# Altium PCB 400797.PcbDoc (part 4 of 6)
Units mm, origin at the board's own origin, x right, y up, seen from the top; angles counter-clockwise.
Board outline 155 x 63.5 mm, 4 copper layers (Top Layer, Mid-Layer 1, Mid-Layer 2, Bottom Layer), stack 1.514 mm thick; 317 components, 286 nets, 1519 pads, 2174 vias.
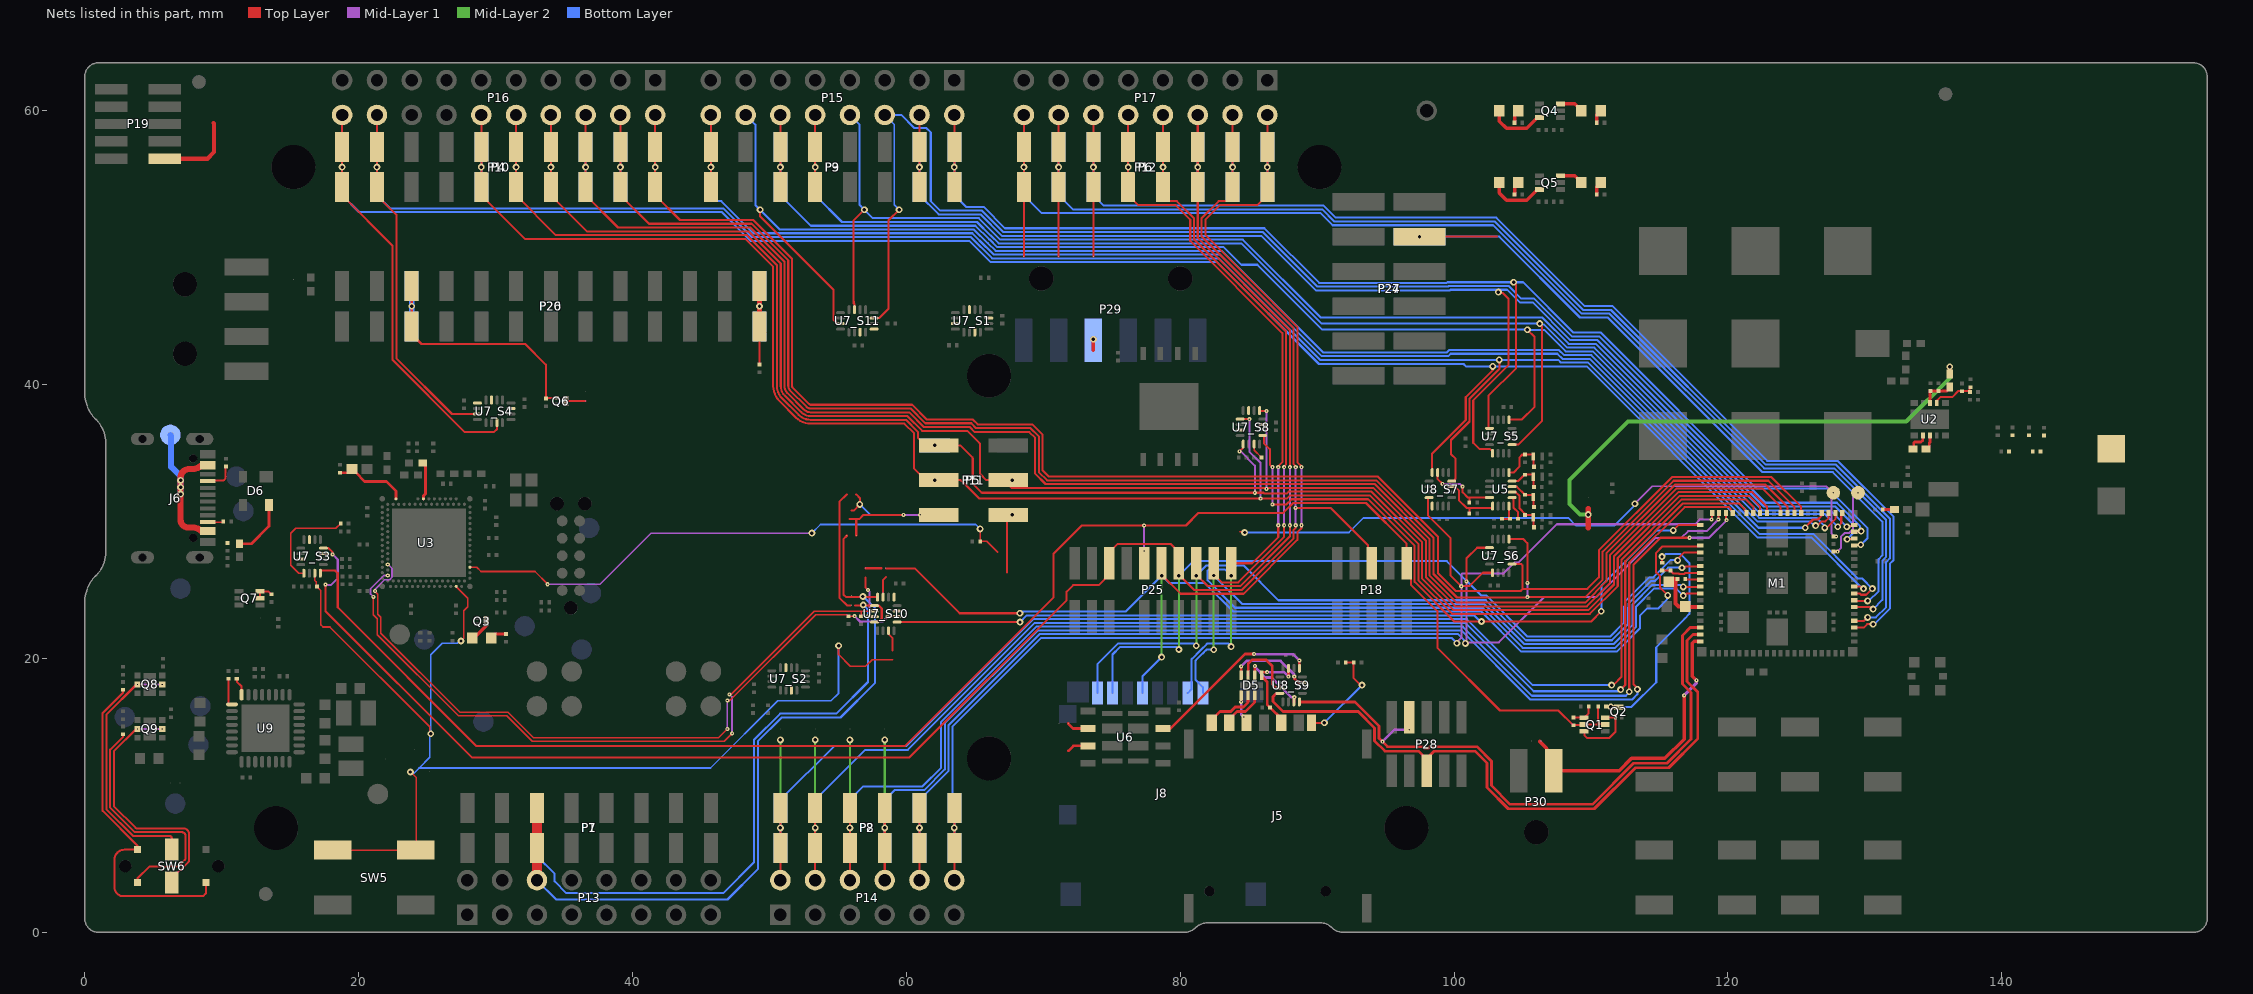
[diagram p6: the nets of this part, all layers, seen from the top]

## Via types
v1: diameter 0.5, hole 0.25, Top Layer to Bottom Layer, tented both sides, 1623 vias
v2: diameter 0.3, hole 0.1, Top Layer to Mid-Layer 1, tented top, 445 vias
v3: diameter 0.3, hole 0.1, Top Layer to Mid-Layer 1, tented both sides, 97 vias
v4: diameter 0.61, hole 0.305, Top Layer to Bottom Layer, tented both sides, 9 vias

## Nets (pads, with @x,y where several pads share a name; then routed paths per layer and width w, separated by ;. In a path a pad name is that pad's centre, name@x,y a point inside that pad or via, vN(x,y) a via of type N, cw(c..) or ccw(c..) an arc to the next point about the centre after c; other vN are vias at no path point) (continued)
NC.CH4_S3: R19.2 U7_S3.13 | length 7.5
  Top Layer w0.125: U7_S3.13@16,26.225 15.625,26.225 15.05,26.8 15.05,29.147 15.412,29.509 18.34,29.509 R19.2@18.69,29.859
NC.CH4_S4: U7_S4.13
NC.CH4_S7: U8_S7.13
NC.CH4_S9: U6.7 U8_S9.13 | length 13
  Top Layer w0.2: U6.7@78.75,14.885 79.285,14.885 84.725,20.325 v2(85.4,20.325) ; U8_S9.13@88.7,19.275 v2(88.7,19.85)
  Mid-Layer 1 w0.2: v2(85.4,20.325) 85.415,20.31 88.24,20.31 v2(88.7,19.85)
NC.CH4_S10: U7_S10.13
NC.CH4_S11: U7_S11.13
NetA1_1: A1.1 C20.2 L2.2
NetC7_1: C7.1 FB1.2 M1.14 R1.1 | length 4.5
  Top Layer w0.3: C7.1@115.675,25.6 115.875,25.8 R1.1@116.315,25.8 116.175,25.66 116.175,24.025 116.4,23.8 FB1.2@116.875,23.8 116.925,23.75 M1.14@117.975,23.75
NetC10_1: C10.1 M1.9 R2.2 | length 2.9
  Top Layer w0.15: R2.2@115.125,26.475 115.14,26.475 R2.2@115.2,26.415 C10.1@115.8,26.415 ; C10.1@115.875,26.34 116.015,26.2 116.411,26.2 116.434,26.177 116.83,26.177 116.903,26.25 M1.9@117.975,26.25
NetC14_2: C14.2 C15.2 FB3.1 U2.3 | length 2.5
  Top Layer w0.2: U2.3@134.747,38.653 C14.2@134.747,39.534 ; C14.2@134.797,39.534 C14.2@134.8,39.537 C15.2@135.375,39.537 135.987,39.537 136.2,39.75 FB3.1@136.2,39.825 FB3.1@136.2,39.9
NetC16_2: C16.2 C17.2 R6.2 U2.2 | length 3.1
  Top Layer w0.15: U2.2@135.247,38.653 135.247,38.819 135.513,39.085 136.385,39.085 136.837,39.537 137.595,39.537 137.625,39.567 137.625,39.755 137.685,39.815 C16.2@137.7,39.815
NetC19_2: C19.2 L4.2 | length 0.8
  Top Layer w0.203: C19.2@131.315,30.88 L4.2@132.155,30.88
NetC20_1: C20.1 C22.2 C23.2 L1.2
NetC36_2: C36.2 U3.A15 | length 2.7
  Top Layer w0.225: C36.2@24.675,34.264 24.875,34.064 24.875,32.009 24.725,31.859 U3.A15@24.725,31.659
NetC37_1: C37.1 R21.2 U3.A5 | length 5.3
  Top Layer w0.15: U3.A5@22.725,31.659 U3.A5@22.75,31.684
  Top Layer w0.18: U3.A5@22.745,31.684 22.745,31.774
  Top Layer w0.2: R21.2@18.625,33.565 19.794,33.565 20.434,32.925 22.026,32.925 22.725,32.225 U3.A5@22.725,31.659
NetC44_1: C44.1 D1.3 R53.1 U5.2 | length 3.6
  Top Layer w0.15: U5.2@104.235,32.15 104.516,32.15 104.78,31.887 104.78,30.963 105.174,30.568 C44.1@105.174,30.476 D1.3@105.784,30.476 ; D1.3@105.789,30.318 105.789,29.621 R53.1@105.829,29.581
NetC45_2: C45.2 D2.3 R55.1 U5.3 | length 2.6
  Top Layer w0.15: U5.3@104.235,32.55 104.581,32.55 C45.2@105.182,31.949 ; C45.2@105.174,31.949 C45.2@105.182,31.949 ; D2.3@105.784,31.949 C45.2@105.182,31.949 ; D2.3@105.789,31.791 105.789,31.095 R55.1@105.829,31.055
NetC46_2: C46.2 D3.3 R57.1 U5.4 | length 2.5
  Top Layer w0.15: U5.4@104.235,32.95 104.67,32.95 105.142,33.422 C46.2@105.174,33.422 D3.3@105.784,33.422 ; D3.3@105.789,33.264 105.789,32.568 R57.1@105.829,32.528
NetC47_2: C47.2 D4.3 R61.1 U5.5 | length 3.5
  Top Layer w0.15: U5.5@104.01,33.575 104.34,33.575 104.771,34.006 104.771,34.669 104.997,34.896 C47.2@105.174,34.896 D4.3@105.784,34.896 ; D4.3@105.789,34.738 105.789,34.041 R61.1@105.829,34.001
NetC50_2: C50.2 D6.4 FB2.1 J6.A4 J6.A9 TP17.1 | length 16.9
  Top Layer w0.2: FB2.1@11.24,28.435 cw(c11.24,28.375) FB2.1@11.3,28.375 12.165,28.375 13.447,29.657 D6.4@13.447,31.209
  Top Layer w0.45: J6.A9@8.985,29.3 8.489,29.3 ccw(c7.915,28.81) 7.896,29.565 7.535,29.565 cw(c7.535,30.1) 7,30.1 v1(7,32) v1(7,32.5) v1(7,33) 7,33.2 cw(c7.635,33.2) 7.635,33.835 7.896,33.835 ccw(c7.915,34.59) 8.489,34.1 J6.A4@8.985,34.1
  Bottom Layer w0.45: TP17.1@6.248,36.324 6.3,36.272 6.3,34 7,33.3 v1(7,33) v1(7,32.5) v1(7,32)
NetD5_1: D5.1 J5.C2 | length 1.7
  Top Layer w0.2: v2(84.45,16.825) D5.1@84.45,17.325
  Mid-Layer 1 w0.2: v2(84.45,16.825) 84.45,15.925 v2(84.65,15.725)
NetD5_2: D5.2 J5.C3 | length 3.9
  Top Layer w0.2: J5.C3@82.3,15.3 82.3,15.525 82.9,16.125 83.69,16.125 84.015,16.45 84.619,16.45 84.95,16.781 D5.2@84.95,17.325
NetD5_3: D5.3 J5.C7 | length 3.2
  Top Layer w0.2: J5.C7@83.57,15.3 83.57,15.545 84.15,16.125 84.753,16.125 85.45,16.822 D5.3@85.45,17.325
NetFB3_2: FB3.2 SB1.2 SB2.2 | length 37.1
  Top Layer w0.3: FB3.2@136.2,40.775 v1(136.2,41.3)
  Top Layer w0.4: SB1.2@109.8,29.55 v1(109.8,30.5) 109.8,30.95
  Mid-Layer 2 w0.3: v1(109.8,30.5) 109.2,30.5 108.425,31.275 108.425,33.025 112.7,37.3 133.02,37.3 136.2,40.48 v1(136.2,41.3)
NetJ5_CD: J5.CD R62.2 R63.2 | length 7.4
  Top Layer w0.15: J5.CD@89.6,15.3 v1(90.525,15.3) ; R63.2@92.085,19.7 R62.2@92.665,19.7 92.665,18.56 93.175,18.05 v1(93.275,18.05)
  Bottom Layer w0.15: v1(90.525,15.3) v1(93.275,18.05)
NetJ6_A5: J6.A5 R71.2 | length 2.2
  Top Layer w0.125: J6.A5@8.985,32.95 9.493,32.987 10.086,32.987 ccw(c10.086,33.112) 10.174,33.024 10.234,33.084 ccw(c10.146,33.172) 10.271,33.172 10.271,33.943 R71.2@10.3,34.015
NetJ6_B5: J6.B5 R70.2 | length 1.1
  Top Layer w0.125: J6.B5@8.985,29.955 10.07,29.955 R70.2@10.115,30
NetL6_1: L6.1 U2.8 | length 1.1
  Top Layer w0.2: L6.1@134.475,35.3 134.55,35.3 134.7,35.45 134.7,35.718 134.747,35.765 U2.8@134.747,36.278
NetL6_2: L6.2 U2.7 | length 1.5
  Top Layer w0.2: L6.2@133.525,35.3 133.575,35.35 133.575,35.733 133.642,35.8 134.1,35.8 134.225,35.925 134.225,36.256 U2.7@134.247,36.278
NetLED1_1: LED1.1 Q4.6 | length 4.1
  Top Layer w0.254: LED1.1@103.301,60 103.301,59.242 103.827,58.716 105.304,58.716 Q4.6@106.039,59.452 ; Q4.6@106.202,59.452 Q4.6@106.25,59.5
NetLED1_2: LED1.2 R39.1 | length 1
  Top Layer w0.254: R39.1@104.414,59.118 104.414,59.69 LED1.2@104.698,59.975
NetLED2_1: LED2.1 Q4.3 | length 1.8
  Top Layer w0.254: Q4.3@107.75,60.5 Q4.3@107.775,60.5 108.801,60.5 109.022,60.279 109.047,60.279 109.301,60.025 LED2.1@109.301,60
NetLED2_2: LED2.2 R40.1 | length 1
  Top Layer w0.254: R40.1@110.414,59.118 110.414,59.69 110.698,59.975 LED2.2@110.698,60
NetLED3_1: LED3.1 Q5.6 | length 4.1
  Top Layer w0.254: LED3.1@103.302,54.75 103.302,53.992 103.827,53.466 105.304,53.466 Q5.6@106.039,54.202 ; Q5.6@106.202,54.202 Q5.6@106.25,54.25
NetLED3_2: LED3.2 R41.1 | length 1
  Top Layer w0.254: R41.1@104.414,53.868 104.414,54.44 104.699,54.725 LED3.2@104.699,54.75
NetLED4_1: LED4.1 Q5.3 | length 1.4
  Top Layer w0.254: Q5.3@107.75,55.25 Q5.3@107.775,55.25 108.801,55.25 LED4.1@109.022,55.029
NetLED4_2: LED4.2 R42.1 | length 1
  Top Layer w0.254: R42.1@110.414,53.868 110.414,54.44 110.698,54.725 LED4.2@110.698,54.75
NetLED5_1: LED5.1 Q3.3 | length 1.7
  Top Layer w0.25: LED5.1@28.302,21.5 28.45,21.5 29.325,22.375 Q3.3@29.325,22.725
NetLED5_2: LED5.2 R33.1 | length 1.2
  Top Layer w0.25: LED5.2@29.699,21.5 29.983,21.785 R33.1@30.75,21.785
NetM1_10: M1.10 R1.2 | length 1.1
  Top Layer w0.15: R1.2@116.885,25.8 116.935,25.75 M1.10@117.975,25.75
NetM1_99: M1.99 TP1.1 | length 5.4
  Top Layer w0.15: M1.99@127.7,27.8 v3(128,27.8)
  Mid-Layer 1 w0.15: v3(128,27.8) 128.25,28.05 128.25,28.886 128.521,29.158 128.863,29.158 129.135,29.429 129.135,31.735 v3(129.5,32.1)
NetM1_101: M1.101 SB11.2 TP2.1 | length 49.2
  Top Layer w0.125: SB11.2@84.35,29.25 84.539,29.25 84.556,29.233 84.667,29.233 v1(84.7,29.2)
  Top Layer w0.15: M1.101@127.7,28.9 127.703,28.903 127.898,28.903 v3(127.901,28.905)
  Mid-Layer 1 w0.125: v1(113.2,31.3) 114.477,32.577 127.176,32.577 127.653,32.1 v3(127.7,32.1)
  Mid-Layer 1 w0.15: v3(127.7,32.1) 127.7,32.087 127.55,31.937 127.55,29.15 127.785,28.915 127.891,28.915 v3(127.901,28.905)
  Bottom Layer w0.125: v1(84.7,29.2) 92.319,29.2 93.381,30.263 108.337,30.263 108.9,29.7 111.7,29.7 113.2,31.2 v1(113.2,31.3)
NetP5_6: P5.6 P11.6 SB18.1 SB19.2 | length 4
  Top Layer w0.152: 67.338,26.275 P5.6@67.338,30.263
  other v1: 67.722,30.481
NetP19_1: P19.1 SB15.1 SB16.1 | length 5.9
  Top Layer w0.3: P19.1@5.836,56.491 8.95,56.491 9.438,56.978 9.438,57.603 9.438,59.057 SB16.1@9.4,59.095
NetP20_3: P20.3 P26.3 Q6.1 R67.1 | length 20.9
  Top Layer w0.15: P20.3@23.876,47.753 P20.3@23.876,47.186 v1(23.876,45.721) P20.3@23.876,44.256 23.876,43.674 24.589,42.961 32.164,42.961 33.675,41.45 R67.1@33.675,39.025 ; R67.1@33.675,38.985 R67.1@33.675,39.025 ; Q6.1@34.425,39.025 R67.1@33.675,39.025
  Bottom Layer w0.381: P26.3@23.876,44.256 v1(23.876,45.721) P26.3@23.876,47.186
NetP20_13: P20.13 P26.13 R68.2 | length 9.3
  Top Layer w0.152: R68.2@49.276,41.46 P20.13@49.276,44.256 49.276,44.204 P20.13@49.71,43.77
  Top Layer w0.381: P20.13@49.276,44.256 v1(49.276,45.721) P20.13@49.276,47.186
  Bottom Layer w0.381: P26.13@49.276,44.256 v1(49.276,45.721) P26.13@49.276,47.186
NetP29_3: P29.3 SB20.2 | length 0.8
  Top Layer w0.254: 73.66,42.517 SB20.2@73.66,42.555 v1(73.66,43.31)
NetQ1_3: Q1.3 Q1.6 Q2.1 | length 4.7
  Top Layer w0.15: Q1.6@109.49,14.675 109.537,14.628 109.537,14.363 109.7,14.2 111.348,14.2 111.79,14.642 Q2.1@111.79,15.725 ; Q1.3@111.04,15.675 111.74,15.675 Q2.1@111.79,15.725 ; Q2.1@111.79,15.75 Q2.1@111.79,15.725
NetQ1_4: Q1.4 R8.2 R10.2 | length 1.7
  Top Layer w0.15: R10.2@108.715,15.685 109.5,15.685 109.825,16.01 R8.2@109.825,16.5
NetQ6_3: Q6.3 SB17.1 | length 1.5
  Top Layer w0.15: Q6.3@35.125,38.8 35.135,38.81 SB17.1@36.576,38.81
NetQ7_5: Q7.5 Q7.6 R75.2 | length 1.4
  Top Layer w0.15: Q7.5@12.8,24.4 Q7.6@12.8,24.9 13.41,24.9 R75.2@13.625,24.685
NetQ8_2: Q8.2 Q8.5 SW6.5 | length 18.4
  Top Layer w0.15: 3.485,7.079 ccw(c3.591,7.185) 3.591,7.035 6.2,7.035 cw(c6.2,6.885) 6.35,6.885 SW6.5@6.35,6.035 ; 3.485,7.079 1.575,8.989 1.575,15.898 3.777,18.1 v2(3.845,18.1)
  Mid-Layer 1 w0.15: v2(3.845,18.1) v2(5.655,18.1)
NetQ9_2: Q9.2 Q9.5 SW6.2 | length 18.7
  Top Layer w0.15: 3.713,7.629 2.125,9.217 2.125,13.222 3.753,14.85 v2(3.845,14.85) ; 3.713,7.629 ccw(c3.819,7.735) 3.819,7.585 7.215,7.585 cw(c7.215,7.435) 7.231,7.584 7.246,7.583 cw(c7.2,7.16) 7.622,7.206 7.624,7.191 cw(c7.475,7.175) 7.625,7.175 7.625,5.272 cw(c7.475,5.272) 7.581,5.166 6.35,3.935 SW6.2@6.35,3.635
  Mid-Layer 1 w0.15: v2(3.845,14.85) v2(5.655,14.85)
NetR36_1: R36.1 U9.17 | length 2.1
  Top Layer w0.15: R36.1@10.5,18.515 10.5,16.719 10.569,16.65 U9.17@10.75,16.65
NetR37_1: R37.1 U9.16 | length 1.3
  Top Layer w0.15: R37.1@11.1,18.515 11.1,18.3 11.45,17.95 U9.16@11.45,17.35
NetR51_1: R51.1 U5.1 | length 1.7
  Top Layer w0.15: U5.1@104.235,31.75 104.34,31.645 104.34,31.014 104.68,30.674 R51.1@104.68,30.197
NetR58_1: R58.1 R59.2 U5.16 | length 1.5
  Top Layer w0.15: R59.2@103.511,30.197 R58.1@104.095,30.197 104.01,30.282 U5.16@104.01,31.125
NetR77_2: R77.2 SW6.3 SW6.4 | length 25.4
  Top Layer w0.15: R77.2@2.8,17.715 2.8,17.512 1.3,16.012 1.3,8.875 3.85,6.325 SW6.4@3.85,6.035 2.901,6.035 ccw(c2.901,5.309) 2.175,5.309 2.175,3.279 ccw(c2.819,3.279) 2.819,2.635 8.573,2.635 ccw(c8.573,2.785) 8.679,2.679 8.806,2.806 ccw(c8.7,2.912) 8.85,2.912 SW6.3@8.85,3.635
NetR79_1: R79.1 SW6.1 | length 18.2
  Top Layer w0.15: R79.1@2.8,14.465 2.8,14.286 1.85,13.336 1.85,9.103 3.599,7.354 ccw(c3.705,7.46) 3.705,7.31 7.09,7.31 cw(c7.09,7.05) 7.35,7.05 7.35,5.397 cw(c7.2,5.397) 7.306,5.291 6.815,4.8 4.715,4.8 3.85,3.935 SW6.1@3.85,3.635
NetSB13_1: SB13.1 U6.2 | length 1.6
  Top Layer w0.2: 71.812,15.25 72.177,14.885 U6.2@73.25,14.885
NetSB14_1: SB14.1 U6.3 | length 1.6
  Top Layer w0.2: SB14.1@71.838,13.25 72.203,13.615 U6.3@73.25,13.615
NO.CH1_S1: U7_S1.15
NO.CH1_S8: R35.1 U7_S8.15 | length 1.2
  Top Layer w0.125: U7_S8.15@85.4,35.65 85.4,35.209 R35.1@85.938,34.671
NO.CH1_S9: C48.1 D5.5 J5.C1 U8_S9.15 | length 6.8
  Top Layer w0.2: D5.5@85.95,18.775 85.95,18.7 86.35,18.3 86.35,16.635 C48.1@86.56,16.425 87.38,15.605 J5.C1@87.38,15.3 ; D5.5@85.95,19 v2(86.35,19) ; v2(87.9,18.675) U8_S9.15@87.9,19.275
  Mid-Layer 1 w0.2: v2(86.35,19) 87.575,19 v2(87.9,18.675)
NO.CH1_S10: SB22.2 U7_S10.15 | length 1.5
  Top Layer w0.15: U7_S10.15@58.3,24.475 58.3,25.738 58.5,25.938
NO.CH2_S1: U7_S1.3
NO.CH2_S2: U7_S2.3
NO.CH2_S3: U7_S3.3
NO.CH2_S8: U7_S8.3
NO.CH2_S9: D5.7 U8_S9.3 | length 4.9
  Top Layer w0.2: D5.7@84.95,18.775 84.975,18.8 84.975,19.625 85.25,19.9 86.255,19.9 86.725,19.43 86.725,18.111 86.986,17.85 U8_S9.3@87.275,17.85
NO.CH2_S10: SB23.2 U7_S10.3 | length 3.6
  Top Layer w0.15: SB23.2@57,25.912 SB23.2@57,25.9 57,25.2 v2(57.2,25) ; v2(57.15,23.05) U7_S10.3@57.675,23.05
  Mid-Layer 1 w0.15: v2(57.15,23.05) 57.3,23.2 57.3,24.9 v2(57.2,25)
NO.CH3_S1: U7_S1.7
NO.CH3_S3: U7_S3.7
NO.CH3_S4: U7_S4.7
NO.CH3_S8: U7_S8.7
NO.CH3_S9: D5.6 U8_S9.7 | length 4.9
  Top Layer w0.2: D5.6@85.45,18.775 v2(85.45,19.45) ; U8_S9.7@88.3,16.825 88.3,17.15 v2(88.325,17.175)
  Mid-Layer 1 w0.2: v2(85.45,19.45) 85.45,19.37 86.204,18.616 86.659,18.616 88.1,17.175 v2(88.325,17.175)
NO.CH3_S10: SB24.1 U7_S10.7 | length 1.6
  Top Layer w0.15: U7_S10.7@58.7,22.025 58.7,21.772 59,21.472 SB24.1@59,20.6 SB24.1@59,20.588
NO.CH4_S1: U7_S1.11
NO.CH4_S2: U7_S2.11
NO.CH4_S3: U7_S3.11
NO.CH4_S4: U7_S4.11
NO.CH4_S8: U7_S8.11
NO.CH4_S9: D5.8 U8_S9.11 | length 6.1
  Top Layer w0.2: D5.8@84.45,18.775 v2(84.45,19.425) ; v2(88.325,18.675) 88.325,18.55 88.625,18.25 U8_S9.11@88.925,18.25
  Mid-Layer 1 w0.2: v2(84.45,19.425) 84.85,19.825 87.315,19.825 88.325,18.815 v2(88.325,18.675)
NO.CH4_S10: U7_S10.11
NO.CH4_S11: U7_S11.11
nRESET: Q2.3 R2.1 R9.2 | length 17.6
  Top Layer w0.15: R9.2@111.1,16.5 v1@111.398,16.5 ; v1(111.44,16.459) v1@111.398,16.5 ; Q2.3@112.015,16.45 111.965,16.5 v1@111.398,16.5 ; v1(115.181,27.438) 115.191,27.429 115.191,26.994 R2.1@115.2,26.985
  Bottom Layer w0.15: v1(111.44,16.459) 112.959,16.459 114.762,18.262 114.762,20.812 116.837,22.887 116.837,22.905 117.188,23.255 117.188,26.973 116.548,27.613 115.444,27.613 115.269,27.438 v1(115.181,27.438)
P0.00: M1.56 P3.1 P9.1 P15.2 U7_S5.1 | length 99.1
  Top Layer w0.15: P3.1@63.5,54.416 v1(63.5,55.881) P3.1@63.5,57.346 P15.2@63.5,59.691 ; U7_S5.1@102.585,36.809 102.5,36.894 102.5,39.172 104.535,41.207 104.535,47.29 v1(104.35,47.475) ; M1.56@129.225,28.25 129.375,28.275 129.604,28.275 ccw(c129.603,28.425) v1(129.694,28.306)
  Bottom Layer w0.15: P9.1@63.5,57.346 v1(63.5,55.881) P9.1@63.5,54.416 63.5,53.831 64.356,52.975 65.639,52.975 67.198,51.416 86.148,51.416 90.138,47.426 99.46,47.426 99.509,47.475 v1(104.35,47.475) 105.041,47.475 108.715,43.8 110.7,43.8 122.1,32.4 127.314,32.4 130.175,29.539 130.175,28.775 130.089,28.689 129.734,28.334 cw(c129.628,28.44) v1(129.694,28.306)
P0.01: M1.57 P3.2 P9.2 P15.4 U7_S5.5 | length 103.3
  Top Layer w0.15: P3.2@60.96,54.416 v1(60.96,55.881) P3.2@60.96,57.346 P15.4@60.96,59.691 ; U7_S5.5@102.81,34.984 102.81,35.099 102.61,35.299 101.851,35.299 101.4,35.75 101.4,38.85 103.985,41.435 103.985,46.249 103.545,46.689 103.296,46.689 v1(103.235,46.75) ; v1(128.7,28.7) 128.725,28.725 129.2,28.725 M1.57@129.225,28.75
  Bottom Layer w0.15: P9.2@60.96,57.346 v1(60.96,55.881) P9.2@60.96,54.416 60.96,53.831 62.366,52.425 65.411,52.425 66.97,50.866 85.92,50.866 89.91,46.876 99.688,46.876 99.737,46.925 v1@103.235,46.925 ; v1(103.235,46.75) v1@103.235,46.925 ; v1(128.7,28.7) 129.135,29.135 129.135,29.802 127.842,31.094 122.628,31.094 110.472,43.25 108.488,43.25 105.738,46 104.799,46 103.874,46.925 v1@103.235,46.925
P0.02: M1.58 P15.6 U7_S11.15 | length 103.8
  Top Layer w0.15: U7_S11.15@57.643,44.85 58,44.85 58.695,45.545 58.695,51.992 v1(59.473,52.77) ; M1.58@129.225,29.25 129.25,29.275 129.7,29.275 v1(129.725,29.3)
  Bottom Layer w0.125: P15.6@58.42,59.691 58.518,59.593 59.118,58.993 59.118,53.126 v1(59.473,52.77)
  Bottom Layer w0.15: P15.6@58.518,59.593 58.616,59.691 59.616,59.691 60.566,58.741 61.453,58.741 61.78,58.414 61.78,53.4 62.48,52.7 65.525,52.7 67.084,51.141 86.034,51.141 90.024,47.151 99.574,47.151 99.623,47.2 103.988,47.2 104.913,46.275 105.852,46.275 108.602,43.525 110.586,43.525 122.742,31.369 127.956,31.369 129.658,29.667 129.658,29.367 v1(129.725,29.3)
P0.03: M1.59 P15.8 U7_S11.3 | length 97
  Top Layer w0.15: U7_S11.3@56.218,45.475 56.218,45.875 56.156,45.938 56.156,46.051 56.155,51.992 v1(56.933,52.77) ; v1(128.685,29.615) 128.752,29.682 129.157,29.682 M1.59@129.225,29.75
  Bottom Layer w0.15: P15.8@55.88,59.691 56.59,58.981 56.59,53.114 v1(56.933,52.77) 57.554,52.15 65.297,52.15 66.856,50.591 84.573,50.591 90.278,44.886 100.072,44.886 100.086,44.9 106.449,44.9 108.374,42.975 110.358,42.975 122.514,30.819 127.481,30.819 v1(128.685,29.615)
P0.04: M1.61 P3.5 P9.5 P15.10 U7_S5.9 | length 104.7
  Top Layer w0.15: P3.5@53.34,54.416 P3.5@53.34,57.346 P15.10@53.34,59.691 ; U7_S5.9@104.235,35.609 104.693,35.609 106.429,37.344 106.429,44.274 v1(106.252,44.45) ; v1(128.015,29.615) 128.015,29.618 128.275,29.878 128.275,30.55 M1.61@128.35,30.625
  Bottom Layer w0.15: P9.5@53.34,57.346 v1(53.34,55.881) P9.5@53.34,54.416 53.34,53.831 55.296,51.875 65.158,51.875 66.158,50.875 66.183,50.875 66.742,50.316 84.459,50.316 90.325,44.45 v1(106.252,44.45) 106.319,44.383 106.577,44.383 108.26,42.7 110.245,42.7 122.4,30.544 127.086,30.544 v1(128.015,29.615)
P0.05: M1.62 P3.6 P9.6 P15.12 U7_S5.13 | length 104.8
  Top Layer w0.15: P3.6@50.8,54.416 P3.6@50.8,57.346 P15.12@50.8,59.691 ; U7_S5.13@104.01,37.434 104.92,37.434 105.879,38.393 105.879,43.471 v1(105.35,44) ; v1(127.071,29.536) 127.138,29.603 127.278,29.603 127.85,30.175 M1.62@127.85,30.625
  Bottom Layer w0.15: P9.6@50.8,57.346 v1(50.8,55.881) P9.6@50.8,54.416 50.8,53.831 53.031,51.6 65.044,51.6 66.044,50.6 66.069,50.6 66.628,50.041 83.173,50.041 84.464,48.75 85.636,48.75 90.37,44.016 105.334,44.016 v1(105.35,44) 106.571,44 108.146,42.425 110.131,42.425 122.286,30.269 126.467,30.269 127.004,29.732 127.004,29.603 v1(127.071,29.536)
P0.06: M1.63 P15.14 U7_S11.7 | length 106.6
  Top Layer w0.15: v1(49.313,52.77) 49.313,52.298 54.668,46.943 54.668,44.722 54.94,44.45 U7_S11.7@55.193,44.45 ; v1(126.4,29.7) 126.519,29.7 126.572,29.753 126.606,29.753 126.862,30.008 127.108,30.008 127.35,30.25 M1.63@127.35,30.625
  Bottom Layer w0.15: P15.14@48.26,59.691 48.97,58.981 48.97,53.114 v1(49.313,52.77) 50.759,51.325 64.93,51.325 65.93,50.325 65.955,50.325 66.514,49.766 83.034,49.766 90.454,42.346 99.46,42.346 99.639,42.525 107.657,42.525 108.032,42.15 110.017,42.15 122.172,29.994 126.023,29.994 126.317,29.7 v1(126.4,29.7)
P0.07: M1.64 P3.8 P9.8 P15.16 | length 100.7
  Top Layer w0.15: P3.8@45.72,54.416 P3.8@45.72,57.346 P15.16@45.72,59.691 ; v1(125.648,29.544) 125.648,29.584 126.214,30.15 126.573,30.15 126.85,30.427 M1.64@126.85,30.625
  Bottom Layer w0.15: P9.8@45.72,57.346 v1(45.72,55.881) P9.8@45.72,54.416 45.72,53.831 46.155,53.396 46.486,53.396 48.832,51.05 64.817,51.05 65.817,50.05 65.841,50.05 66.4,49.491 82.92,49.491 90.34,42.071 99.574,42.071 99.753,42.25 107.543,42.25 107.918,41.875 109.903,41.875 122.233,29.544 v1(125.648,29.544)
P0.08: M1.67 P4.1 P10.1 P16.2 U7_S6.1 | length 121.5
  Top Layer w0.15: P16.2@41.656,59.691 P4.1@41.656,57.346 v1(41.656,55.881) P4.1@41.656,54.416 41.656,53.831 43.468,52.019 48.814,52.019 51.65,49.183 51.65,39.887 ccw(c51.8,39.887) 51.694,39.781 52.906,38.569 ccw(c53.012,38.675) 53.012,38.525 60.425,38.525 61.5,37.45 64.85,37.45 65.2,37.1 69.181,37.1 69.95,36.331 69.95,33.725 70.389,33.286 94.423,33.286 98.825,28.884 98.825,26.225 100.125,24.925 104.851,24.925 105.005,25.079 ; U7_S6.1@104.235,26.884 104.909,26.884 104.997,26.796 104.997,25.088 105.005,25.079 ; M1.67@125.35,30.625 125.35,31.075 123.175,33.25 115.92,33.25 110.575,27.905 110.575,25.93 109.724,25.079 105.005,25.079
  Bottom Layer w0.15: P10.1@41.656,54.416 v1(41.656,55.881) P10.1@41.656,57.346
P0.09: M1.68 P4.2 P10.2 P16.4 U7_S6.5 | length 126.6
  Top Layer w0.15: P16.4@39.116,59.691 P4.2@39.116,57.346 v1(39.116,55.881) P4.2@39.116,54.416 39.116,53.831 41.203,51.744 48.7,51.744 51.375,49.07 51.375,39.887 ccw(c51.8,39.887) 51.498,39.588 52.713,38.373 ccw(c53.012,38.675) 53.012,38.25 60.311,38.25 61.386,37.175 64.736,37.175 65.086,36.825 69.067,36.825 69.675,36.217 69.675,33.611 70.275,33.011 94.309,33.011 98.495,28.825 98.495,26.166 100.211,24.45 105.287,24.45 105.312,24.475 v2(105.35,24.475) 109.584,24.475 110.85,25.741 110.85,27.791 116.034,32.975 122.95,32.975 124.85,31.075 M1.68@124.85,30.625 ; U7_S6.5@104.01,28.709 105.066,28.709 105.354,28.421 v2(105.354,25.521)
  Mid-Layer 1 w0.15: v2(105.35,24.475) 105.352,24.477 105.352,25.518 v2(105.354,25.521)
  Bottom Layer w0.15: P10.2@39.116,54.416 v1(39.116,55.881) P10.2@39.116,57.346
P0.10: M1.69 P4.3 P10.3 P16.6 | length 123.3
  Top Layer w0.15: P16.6@36.576,59.691 P4.3@36.576,57.346 v1(36.576,55.881) P4.3@36.576,54.416 36.576,53.831 38.938,51.469 48.586,51.469 51.1,48.956 51.1,39.887 ccw(c51.8,39.887) 51.302,39.395 52.52,38.178 ccw(c53.012,38.675) 53.012,37.975 60.197,37.975 61.272,36.9 64.622,36.9 64.997,36.525 68.978,36.525 69.4,36.103 69.4,33.497 70.161,32.736 94.196,32.736 98.22,28.712 98.22,26.052 100.197,24.075 109.573,24.075 111.125,25.627 111.125,27.677 116.148,32.7 122.725,32.7 124.35,31.075 M1.69@124.35,30.625
  Bottom Layer w0.15: P10.3@36.576,54.416 v1(36.576,55.881) P10.3@36.576,57.346
P0.11: M1.70 P4.4 P5.4 P10.4 P11.4 P16.8 U7_S8.5 | length 131.5
  Top Layer w0.15: P16.8@34.036,59.691 P4.4@34.036,57.346 v1(34.036,55.881) P4.4@34.036,54.416 34.036,53.824 36.665,51.194 39.881,51.194 39.882,51.193 40.483,51.193 40.485,51.194 48.473,51.194 50.825,48.842 50.825,39.887 ccw(c51.8,39.887) 51.108,39.2 52.325,37.983 ccw(c53.012,38.675) 53.012,37.7 60.083,37.7 61.158,36.625 64.45,36.625 65.331,35.744 cw(c65.225,35.638) 65.375,35.638 65.375,33.537 ccw(c65.525,33.537) 65.418,33.432 ; 65.419,33.431 65.829,33.021 P5.4@67.12,33.021 ; P5.4@67.437,33.021 P5.4@67.12,33.021 ; U7_S8.5@85.8,38.1 85.825,38.075 v2(86.3,38.075) ; v2(86.3,32.386) 86.269,32.417 ccw(c86.163,32.311) 86.163,32.461 67.679,32.461 P5.4@67.12,33.021 ; v2@86.416,32.461 94.082,32.461 97.945,28.598 97.945,25.938 100.083,23.8 109.687,23.8 111.4,25.513 111.4,27.563 116.262,32.425 122.5,32.425 123.85,31.075 M1.70@123.85,30.625
  Mid-Layer 1 w0.15: v2(86.3,32.386) v2(86.3,38.075)
  Bottom Layer w0.15: P10.4@34.036,54.416 v1(34.036,55.881) P10.4@34.036,57.346
  other v1: 67.722,33.021
P0.12: M1.72 P4.5 P5.1 P10.5 P11.1 P16.10 U7_S8.13 | length 130.9
  Top Layer w0.15: P16.10@31.496,59.691 P4.5@31.496,57.346 v1(31.496,55.881) P4.5@31.496,54.416 31.496,53.831 34.408,50.919 39.767,50.919 39.769,50.918 40.597,50.918 40.599,50.919 48.359,50.919 50.55,48.728 50.55,39.887 ccw(c51.8,39.887) 50.914,39.006 52.13,37.789 ccw(c53.012,38.675) 53.012,37.425 59.969,37.425 60.845,36.55 60.845,36.121 61.405,35.561 v1(62.072,35.561) P5.1@62.357,35.561 63.945,35.561 64.803,34.703 cw(c64.697,34.597) 64.847,34.597 64.847,33.672 64.847,32.815 ccw(c64.997,32.815) 64.89,32.71 65.456,32.144 ccw(c65.562,32.25) 65.562,32.1 v2(85.45,32.1) ; v2(84.325,35.125) 84.6,35.4 U7_S8.13@84.6,35.65 ; v2@85.47,32.08 85.491,32.1 86.091,32.1 86.155,32.036 87.761,32.036 87.911,32.186 93.968,32.186 97.67,28.484 97.67,25.824 99.969,23.525 109.801,23.525 111.675,25.399 111.675,27.449 116.376,32.15 119.538,32.15 120.538,32.15 120.541,32.148 121.777,32.148 122.85,31.075 M1.72@122.85,30.625
  Mid-Layer 1 w0.15: v2(84.325,35.125) 84.411,35.125 85.45,34.086 v2(85.45,32.1)
  Bottom Layer w0.15: P10.5@31.496,54.416 v1(31.496,55.881) P10.5@31.496,57.346
P0.13/AIN0: M1.73 P4.6 P5.3 P10.6 P11.3 P16.12 U7_S8.9 | length 135.8
  Top Layer w0.15: P16.12@28.956,59.691 P4.6@28.956,57.346 v1(28.956,55.881) P4.6@28.956,54.416 28.956,53.831 32.143,50.644 39.653,50.644 39.655,50.643 40.711,50.643 40.713,50.644 48.245,50.644 50.275,48.614 50.275,39.887 ccw(c51.8,39.887) 50.72,38.811 51.936,37.595 ccw(c53.012,38.675) 53.012,37.15 59.855,37.15 60.569,36.436 60.569,33.856 61.405,33.021 P5.3@62.357,33.021 63.917,33.021 cw(c63.917,32.871) 64.023,32.977 65.281,31.719 ccw(c65.387,31.825) 65.387,31.675 v2(85.875,31.675) ; U7_S8.9@84.375,37.475 v2(85.05,37.475) ; v2@85.944,31.675 87.789,31.675 88.025,31.911 93.854,31.911 97.395,28.37 97.395,25.71 99.855,23.25 109.915,23.25 111.95,25.285 111.95,27.335 116.49,31.875 119.425,31.875 120.425,31.875 120.427,31.873 121.552,31.873 122.35,31.075 M1.73@122.35,30.625
  Mid-Layer 1 w0.15: v2(85.05,37.475) 85.05,35.1 85.875,34.275 v2(85.875,31.675)
  Bottom Layer w0.15: P10.6@28.956,54.416 v1(28.956,55.881) P10.6@28.956,57.346
  other v1: 62.072,33.021
P0.14/AIN1: M1.74 P2.1 P8.1 P14.2 SB5.1 | length 105
  Top Layer w0.15: P14.2@50.8,3.811 P2.1@50.8,6.156 v1(50.8,7.621) P2.1@50.8,9.086 ; v1(111.5,18.055) 111.567,18.122 111.692,18.122 112.225,18.655 112.225,27.221 116.604,31.6 119.311,31.6 120.311,31.6 120.313,31.598 121.327,31.598 121.85,31.075 M1.74@121.85,30.625
  Mid-Layer 2 w0.15: v1(50.8,7.621) v1(50.8,14.05)
  Bottom Layer w0.15: P8.1@50.8,6.156 v1(50.8,7.621) P8.1@50.8,9.086 50.8,9.671 54.729,13.6 59.994,13.6 69.269,22.875 100.925,22.875 105.745,18.055 v1(111.5,18.055)
P0.15/AIN2: M1.75 P2.2 P8.2 P14.4 SB6.1 | length 102
  Top Layer w0.15: P14.4@53.34,3.811 P2.2@53.34,9.086 ; v1@112.165,17.726 112.5,18.062 112.5,27.107 116.718,31.325 119.197,31.325 120.197,31.325 120.199,31.323 120.81,31.323 121.2,30.933 121.2,30.85 121.35,30.7 M1.75@121.35,30.625
  Mid-Layer 2 w0.15: v1(53.34,7.621) v1(53.34,14.05)
  Bottom Layer w0.15: P8.2@53.34,6.156 v1(53.34,7.621) P8.2@53.34,9.086 53.34,9.671 56.994,13.325 60.108,13.325 69.383,22.6 100.811,22.6 105.806,17.605 111.95,17.605 112.07,17.725 v1(112.165,17.725)
P0.16/AIN3: M1.77 P2.3 P8.3 P14.6 SB9.1 | length 100.5
  Top Layer w0.15: P14.6@55.88,3.811 P2.3@55.88,6.156 v1(55.88,7.621) P2.3@55.88,9.086 ; v1(112.792,17.569) 112.792,27.01 116.832,31.05 119.083,31.05 120.083,31.05 120.2,30.933 120.2,30.85 120.35,30.7 M1.77@120.35,30.625
  Mid-Layer 2 w0.15: v1(55.88,7.621) v1(55.88,14.05)
  Bottom Layer w0.15: P8.3@55.88,6.156 v1(55.88,7.621) P8.3@55.88,9.086 55.88,9.671 56.865,10.656 61.178,10.656 62.539,12.017 62.539,15.367 69.497,22.325 100.632,22.325 105.682,17.275 112.538,17.275 112.792,17.529 v1(112.792,17.569)
P0.17/AIN4: M1.78 P2.4 P8.4 P14.8 SB10.1 | length 97.8
  Top Layer w0.15: P14.8@58.42,3.811 P2.4@58.42,6.156 v1(58.42,7.621) P2.4@58.42,9.086 ; v1(113.39,17.748) 113.39,17.839 113.1,18.129 113.1,26.84 115.072,28.813 v3(117.2,28.813) ; M1.78@119.85,30.625 119.85,30.191 119.9,30.141 v3(119.9,30.1)
  Mid-Layer 1 w0.15: v3(117.2,28.813) 118.613,28.813 v3(119.9,30.1)
  Mid-Layer 2 w0.15: v1(58.42,7.621) v1(58.42,14.05)
  Bottom Layer w0.15: P8.4@58.42,6.156 v1(58.42,7.621) P8.4@58.42,9.086 58.42,9.671 59.13,10.381 61.292,10.381 62.814,11.903 62.814,15.253 69.611,22.05 100.518,22.05 105.568,17 113,17 113.383,17.383 113.383,17.741 v1(113.39,17.748)
P0.18/AIN5: M1.79 P2.5 P8.5 P14.10 U7_S6.9 | length 86.8
  Top Layer w0.15: P14.10@60.96,3.811 P2.5@60.96,6.156 v1(60.96,7.621) P2.5@60.96,9.086 ; v2(100.9,25.625) 100.9,27.3 101.684,28.084 U7_S6.9@102.585,28.084 ; v3(119.3,30.15) 119.325,30.175 119.325,30.6 M1.79@119.35,30.625
  Mid-Layer 1 w0.15: v1(100.828,21.103) v1@100.9,21.175 ; v2(100.9,25.625) v1@100.9,21.175 ; v3(119.3,30.15) 118.45,29.3 117.1,29.3 116.6,28.8 114.711,28.8 110.411,24.5 106.6,24.5 103.275,21.175 v1@100.9,21.175
  Bottom Layer w0.15: P8.5@60.96,6.156 v1(60.96,7.621) P8.5@60.96,9.086 60.96,9.671 61.395,10.106 61.406,10.106 63.089,11.789 63.089,15.139 69.725,21.775 100.3,21.775 100.714,21.361 100.714,21.312 100.828,21.198 v1(100.828,21.103)
P0.19/AIN6: M1.80 P2.6 P8.6 P14.12 U7_S6.13 U8_S7.12 | length 89.7
  Top Layer w0.15: P14.12@63.5,3.811 P2.6@63.5,6.156 v1(63.5,7.621) P2.6@63.5,9.086 ; U8_S7.12@98.175,31.75 98.122,31.75 98.09,31.718 98.09,30.446 99.725,28.811 99.725,26.075 v2(100.525,25.275) 101.114,25.275 102.098,26.259 U7_S6.13@102.81,26.259 ; v3(118.8,30.15) 118.825,30.175 118.825,30.6 M1.80@118.85,30.625
  Mid-Layer 1 w0.15: v1(100.2,21.113) 100.2,21.175 100.525,21.5 v2(100.525,25.275) 100.525,26.112 100.613,26.2 103.6,26.2 104.4,27 104.7,27 107.5,29.8 117.6,29.8 117.95,30.15 v3(118.8,30.15)
  Bottom Layer w0.15: P8.6@63.5,6.156 v1(63.5,7.621) P8.6@63.5,9.086 63.364,9.222 63.364,15.025 69.839,21.5 99.812,21.5 v1(100.2,21.113)
P0.20/AIN7: M1.2 U7_S8.1 U7_S10.9 | length 89
  Top Layer w0.15: U7_S10.9@59.325,22.65 v1(68.3,22.65) ; U7_S8.1@86.025,36.275 86.11,36.19 86.11,35.729 86.548,35.291 86.548,34.155 v2(86.734,33.969) ; v2(86.725,31.25) 87.761,31.25 88.136,31.625 93.728,31.625 97.12,28.233 97.12,25.597 100.017,22.7 v1(102,22.7) 110.003,22.7 v1(110.751,23.449) ; v1(116,29.35) 116.4,29.75 M1.2@117.975,29.75
  Mid-Layer 1 w0.15: v2(86.725,31.25) 86.729,31.254 86.729,33.965 v2@86.725,33.969
  Bottom Layer w0.15: v1(68.3,22.65) 68.8,23.15 101.455,23.15 101.905,22.7 v1(102,22.7) ; v1(110.751,23.449) 110.751,25.294 114.808,29.35 v1(116,29.35)
P0.21: J8.5 M1.5 P6.1 P12.1 P17.2 P25.12 SB22.1 SB23.1 | length 134.2
  Top Layer w0.15: SB23.1@57,26.588 58.168,26.588 ; 58.5,26.562 58.5,26.575 60.018,26.575 60.031,26.562 60.638,26.562 63.9,23.3 v1(68.292,23.3) ; P25.12@78.667,26.083 80.025,24.725 84.625,24.725 88.559,28.659 88.559,29.209 88.853,29.503 88.853,29.722 v2(88.859,29.728) ; P17.2@86.36,59.691 P6.1@86.36,57.346 P6.1@86.36,54.416 86.36,53.831 85.65,53.121 82.914,53.121 81.83,52.037 81.83,50.945 88.559,44.216 88.559,34.339 88.859,34.039 v2(88.859,33.969) ; v1@115.505,24.6 v1(115.6,24.6) 115.05,25.15 115.05,25.997 114.731,26.316 114.731,27.694 115.213,28.175 117.9,28.175 M1.5@117.975,28.25
  Mid-Layer 1 w0.15: v2(88.859,29.728) v2(88.859,33.969)
  Mid-Layer 2 w0.15: v1(78.635,20.1) v1(78.635,26.05)
  Bottom Layer w0.15: v1(68.292,23.3) 68.387,23.3 68.512,23.425 76.01,23.425 v1(78.635,26.05) 79.185,25.5 81.8,25.5 83.875,23.425 101.975,23.425 104.897,20.503 111.881,20.503 113.566,22.188 113.566,23.127 114.082,23.643 114.893,23.643 115.539,24.289 115.539,24.539 v1(115.6,24.6) ; J8.5@77.25,17.47 77.25,18.715 v1(78.635,20.1) ; P12.1@86.36,54.416 P12.1@86.36,57.346
  other v1: 86.36,55.881
P0.22: J8.7 M1.6 P6.2 P12.2 P17.4 P18.6 P25.6 P25.14 U7_S3.4 | length 195.1
  Top Layer w0.15: U7_S3.4@17.425,28.05 17.8,28.05 18.1,27.75 v2(18.1,27.6) ; v2(17.575,25.4) 17.575,23.463 28.263,12.775 60.228,12.775 71.7,24.247 71.7,24.87 72.178,25.347 74.042,25.347 74.825,26.13 P25.6@74.825,26.95 74.825,27.77 75.405,28.35 79.325,28.35 79.905,27.77 P25.14@79.905,26.95 79.905,26.13 81.035,25 84.5,25 88.284,28.784 88.284,29.384 88.405,29.505 88.405,29.699 v2(88.434,29.728) ; P6.2@83.675,53.396 82.8,53.396 81.555,52.151 81.555,50.831 88.284,44.103 88.284,34.189 88.434,34.039 v2(88.434,33.969) ; P6.2@83.82,54.662 v1(83.82,55.881) P6.2@83.82,57.346 P17.4@83.82,59.691 ; v2(88.425,31) 90.975,31 93.713,28.262 93.713,27.237 P18.6@94,26.95 ; v1(116.322,27.163) 116.322,27.258 116.455,27.391 116.455,27.403 116.803,27.75 M1.6@117.975,27.75
  Mid-Layer 1 w0.15: v2(17.575,25.4) 17.6,25.375 17.995,25.375 18.475,25.855 18.475,27.225 v2(18.1,27.6) ; v2(88.434,29.728) v2(88.434,33.969)
  Mid-Layer 2 w0.15: v1(79.905,20.65) v1(79.905,26.05)
  Bottom Layer w0.15: J8.7@75.05,17.47 75.05,20.289 75.586,20.825 79.73,20.825 v1(79.905,20.65) ; v1(79.905,26.05) 80.955,27.1 99.463,27.1 101.963,24.6 102.356,24.6 105.353,21.603 111.403,21.603 112.4,22.6 112.4,23.774 112.466,23.84 112.466,24.132 114.252,25.919 114.545,25.919 115.827,27.201 116.285,27.201 v1(116.322,27.163) ; P12.2@83.82,54.416 P12.2@83.82,57.346
P0.23: J8.8 M1.8 P6.3 P12.3 P17.6 P25.16 | length 103.7
  Top Layer w0.15: P25.16@81.175,26.95 81.175,26.125 81.18,26.125 82.03,25.275 84.375,25.275 88.009,28.909 v2(88.009,29.728) ; P17.6@81.28,59.691 P6.3@81.28,57.346 v1(81.28,55.881) P6.3@81.28,54.416 81.28,50.717 88.009,43.989 v2(88.009,33.969) ; v1(116.643,26.627) 116.71,26.694 116.875,26.694 116.906,26.725 117.95,26.725 M1.8@117.975,26.75
  Mid-Layer 1 w0.15: v2(88.009,29.728) v2(88.009,33.969)
  Mid-Layer 2 w0.15: v1(81.175,20.923) ccw(c81.025,20.931) 81.175,20.931 v1(81.175,26.05)
  Bottom Layer w0.15: J8.8@73.95,17.47 73.95,19.578 75.472,21.1 81,21.1 81.161,20.939 cw(c81.055,20.833) v1(81.175,20.923) ; v1(81.175,26.05) 81.909,26.784 84.63,26.784 87.164,24.25 102.317,24.25 105.239,21.328 111.528,21.328 112.7,22.5 112.7,23.685 112.741,23.726 112.741,24.018 114.366,25.644 114.659,25.644 115.642,26.627 v1(116.643,26.627) ; P12.3@81.28,54.416 P12.3@81.28,57.346
P0.24: J8.1 M1.11 P6.4 P12.4 P17.8 P25.18 | length 94.9
  Top Layer w0.15: P6.4@78.6,53.396 79.76,53.396 81.005,52.151 81.005,50.603 87.734,43.875 87.734,34.189 87.584,34.039 v2(87.584,33.969) ; P6.4@78.74,54.416 P17.8@78.74,59.691 ; P25.18@82.445,26.95 82.445,26.13 P25.18@82.485,26.09 ; v1(82.454,26.059) P25.18@82.485,26.09 ; v2(87.584,29.728) 87.584,28.884 84.25,25.55 83.025,25.55 P25.18@82.485,26.09 ; v1(116.738,25.226) 116.741,25.229 117.954,25.229 M1.11@117.975,25.25
  Mid-Layer 1 w0.15: v2(87.584,29.728) v2(87.584,33.969)
  Mid-Layer 2 w0.15: v1(82.445,20.638) 82.445,26.05 v1(82.454,26.059)
  Bottom Layer w0.15: P12.4@78.74,54.416 P12.4@78.74,57.346 ; J8.1@81.65,17.47 81.65,17.91 81.1,18.46 81.1,19.763 cw(c81.25,19.763) 81.143,19.868 81.653,20.378 cw(c81.759,20.271) 81.658,20.383 ccw(c81.175,20.923) 81.715,20.439 cw(c81.826,20.339) 81.72,20.444 81.882,20.606 cw(c81.987,20.5) 81.987,20.65 82.386,20.65 cw(c82.385,20.5) v1(82.445,20.638) ; v1(82.454,26.059) 82.454,26.041 84.52,23.975 102.203,23.975 105.125,21.053 111.653,21.053 113.016,22.416 113.016,23.905 114.48,25.369 116.5,25.369 116.643,25.226 v1(116.738,25.226)
  other v1: 78.74,55.881
P0.25: J8.2 M1.12 P6.5 P12.5 P17.10 P25.20 | length 99.9
  Top Layer w0.15: P6.5@76.2,54.416 76.2,53.831 76.91,53.121 79.646,53.121 80.73,52.037 80.73,50.489 87.459,43.761 87.459,34.339 87.159,34.039 v2(87.159,33.969) ; P6.5@76.2,54.713 v1(76.2,55.881) P6.5@76.2,57.346 P17.10@76.2,59.691 ; v1(83.715,26.05) P25.20@83.715,26.95 85.25,26.95 87.159,28.859 v2(87.159,29.728) ; v1(116.737,24.584) 116.83,24.584 116.996,24.75 M1.12@117.975,24.75
  Mid-Layer 1 w0.15: v2(87.159,29.728) v2(87.159,33.969)
  Mid-Layer 2 w0.15: v1(83.715,20.863) v1(83.715,26.05)
  Bottom Layer w0.15: P12.5@76.2,54.416 P12.5@76.2,57.346 ; J8.2@80.55,17.47 80.825,17.745 80.825,19.876 cw(c80.975,19.876) 80.868,19.982 81.465,20.578 cw(c81.57,20.472) 81.47,20.583 ; 81.47,20.584 ccw(c81.175,20.923) 81.513,20.627 cw(c81.626,20.528) 81.519,20.633 81.93,21.044 cw(c82.036,20.938) 82.036,21.088 83.518,21.088 83.568,21.038 83.677,21.038 cw(c83.565,20.938) 83.715,20.938 v1(83.715,20.863) ; v1(83.715,26.05) 83.256,26.509 82.109,26.509 82.004,26.404 82.004,25.696 84,23.7 102.089,23.7 105.011,20.778 111.767,20.778 113.291,22.302 113.291,23.791 114.594,25.094 116.227,25.094 v1(116.737,24.584)
P0.26: M1.44 P6.6 P12.6 P17.12 SB3.1 | length 92
  Top Layer w0.15: SB3.1@73.66,49.338 SB3.1@73.66,49.35 P6.6@73.66,54.416 P6.6@73.66,57.346 P17.12@73.66,59.691 ; M1.44@129.225,22.25 129.914,22.25 130.164,22.5 v1(130.6,22.5)
  Bottom Layer w0.15: P12.6@73.66,57.346 v1(73.66,55.881) P12.6@73.66,54.416 73.66,53.831 74.424,53.067 90.479,53.067 91.36,52.186 103.079,52.186 109.54,45.725 111.575,45.725 122.867,34.433 128.003,34.433 132.1,30.337 132.1,27.189 131.825,26.914 131.825,23.636 130.689,22.5 v1(130.6,22.5)
P0.27: M1.45 P6.7 P12.7 P17.14 SB4.1 | length 93.7
  Top Layer w0.15: SB4.1@71.12,49.338 P6.7@71.12,54.416 P6.7@71.12,57.346 P17.14@71.12,59.691 ; M1.45@129.225,22.75 129.937,22.75 130.187,23 v1(130.2,23)
  Bottom Layer w0.15: P12.7@71.12,57.346 v1(71.12,55.881) P12.7@71.12,54.416 71.12,53.831 72.159,52.792 90.365,52.792 91.246,51.911 102.965,51.911 109.426,45.45 111.461,45.45 122.753,34.158 127.889,34.158 131.825,30.223 131.825,27.302 131.55,27.027 131.55,23.75 130.8,23 v1(130.2,23)
P0.28: M1.47 P6.8 P12.8 P17.16 SB7.1 | length 95
  Top Layer w0.15: SB7.1@68.58,49.338 SB7.1@68.58,49.35 P6.8@68.58,54.416 P6.8@68.58,57.346 P17.16@68.58,59.691 ; M1.47@129.225,23.75 130.355,23.75 130.505,23.6 v1(130.6,23.6)
  Bottom Layer w0.15: P12.8@68.58,57.346 v1(68.58,55.881) P12.8@68.58,54.416 68.58,53.831 69.894,52.517 90.251,52.517 91.132,51.636 102.851,51.636 109.312,45.175 111.347,45.175 122.639,33.883 127.775,33.883 131.55,30.109 131.55,27.416 131.275,27.141 131.275,24.275 v1(130.6,23.6)
P0.29: M1.48 P24.4 P27.4 SB8.1 | length 55.4
  Top Layer w0.15: v1(97.473,50.801) SB8.1@103.123,50.801 SB8.1@103.135,50.801 ; M1.48@129.225,24.25 129.275,24.2 v1(130.2,24.2)
  Bottom Layer w0.15: v1(97.473,50.801) 103.297,50.801 109.198,44.9 111.233,44.9 122.525,33.608 127.661,33.608 131.275,29.995 131.275,27.53 131,27.255 131,24.914 130.286,24.2 v1(130.2,24.2)
P0.30: M1.49 P4.9 P10.9 P16.18 U7_S4.15 U8_S7.4 | length 162.2
  Top Layer w0.15: P4.9@21.336,53.824 22.75,52.41 22.75,41.914 26.814,37.85 U7_S4.15@28.675,37.85 ; P4.9@21.336,54.416 v1(21.336,55.881) P4.9@21.336,57.346 P16.18@21.336,59.691 ; U8_S7.4@99.825,32.95 99.93,32.95 100.118,33.137 100.118,34.582 99.775,34.925 99.775,35.95 101.125,37.3 101.125,38.964 103.3,41.139 v1(103.3,41.8) ; M1.49@129.225,24.75 129.614,24.75 129.714,24.65 130.086,24.65 130.536,25.1 v1(130.55,25.1)
  Bottom Layer w0.15: P10.9@21.336,57.346 v1(21.336,55.881) P10.9@21.336,54.416 21.336,53.831 22.292,52.875 46.618,52.875 48.718,50.775 64.703,50.775 66.262,49.216 82.806,49.216 90.226,41.796 103.3,41.796 103.304,41.8 107.604,41.8 107.804,41.6 109.789,41.6 122.294,29.094 126.222,29.094 129.495,25.822 129.828,25.822 v1(130.55,25.1)
P0.31: M1.50 P4.10 P10.10 P16.20 U7_S4.3 U8_S7.8 | length 166
  Top Layer w0.15: P4.10@18.796,53.831 22.475,50.152 22.475,41.8 27.75,36.525 29.875,36.525 30.1,36.75 U7_S4.3@30.1,37.225 ; P4.10@18.796,54.416 v1(18.796,55.881) P4.10@18.796,57.346 P16.20@18.796,59.691 ; U8_S7.8@98.4,33.575 98.4,34.964 100.85,37.414 100.85,39.078 102.825,41.053 v1(102.825,41.325) ; M1.50@129.225,25.25 129.655,25.25 129.805,25.1 v1(129.9,25.1)
  Bottom Layer w0.15: P10.10@18.796,57.346 v1(18.796,55.881) P10.10@18.796,54.416 18.796,53.831 20.027,52.6 46.504,52.6 48.604,50.5 64.589,50.5 66.148,48.941 82.692,48.941 90.133,41.5 100.686,41.5 100.861,41.325 v1(102.825,41.325) 109.675,41.325 122.181,28.819 126.108,28.819 129.828,25.1 v1(129.9,25.1)
RESET: P18.10 P25.10 Q1.2 Q1.5 R9.1 R10.1 U7_S3.16 | length 123.1
  Top Layer w0.15: U7_S3.16@17.2,26.225 17.2,26.393 17.232,26.425 18.27,26.425 18.475,26.22 18.475,23.729 28.604,13.6 59.886,13.6 70.75,24.464 70.75,27.667 72.793,29.71 v2(77.365,29.71) 80.418,29.71 81.336,30.628 87.528,30.628 88.25,31.35 93.565,31.35 96.54,28.375 P18.10@96.54,26.95 96.845,26.645 96.845,25.386 98.775,23.456 98.775,20.776 103.351,16.2 107.615,16.2 108.7,15.115 R10.1@108.715,15.115 108.745,15.145 109.46,15.145 Q1.5@109.49,15.175 ; Q1.5@109.49,15.2 109.55,15.2 109.575,15.175 110.515,15.175 ; R9.1@110.53,16.5 110.515,16.485 110.515,15.417 110.515,15.2 111.015,15.2 Q1.2@111.04,15.175
  Mid-Layer 1 w0.15: v2(77.365,27.85) v2(77.365,29.71)
RESET_BOTTOM: P7.3 SB25.1 SB27.1 U7_S10.1 U7_S10.4 | length 58.8
  Top Layer w0.15: SB25.1@55.662,31.981 55.113,31.431 55.113,24.438 55.7,23.85 55.929,23.85 ; 56.264,23.85 U7_S10.1@57.675,23.85 58,23.85 58.2,23.65 58.2,22.922 57.928,22.65 U7_S10.4@57.675,22.65
  Bottom Layer w0.15: P7.3@33.02,6.156 33.02,5.571 34.311,4.28 34.311,3.717 35.166,2.861 46.632,2.861 48.875,5.104 48.875,14.062 50.788,15.975 54.892,15.975 57.2,18.283 57.2,23.55 v1(56.85,23.9)
  Bottom Layer w0.381: P7.3@33.02,6.156 P7.3@33.02,9.086
RESET_BUTTON: R23.1 SB21.2 SB24.2 SW5.2 U3.AL27 U7_S3.15 | length 85.6
  Top Layer w0.125: U7_S3.15@16.8,26.225 16.8,25.696 16.908,25.588 16.908,25.302 R23.1@16.96,25.25 16.96,25.235 17.237,24.958 17.237,22.463 17.4,22.3 17.9,22.3 25.2,15 25.2,14.567 v1(25.27,14.496) ; SW5.2@18.111,6 SW5.2@24.161,6 24.2,6.039 24.2,11.3 23.792,11.708 v1(23.776,11.708) ; U3.AL27@27.125,25.235 27.967,24.393 27.967,23.767 27.675,23.475 27.675,21.475 v1(27.475,21.275) ; v1(55.05,20.925) 55.05,20.285 55.91,19.425 57.013,19.425 57.5,19.912 SB24.2@59,19.912
  Bottom Layer w0.125: v1(23.776,11.708) 23.884,11.6 24.014,11.6 24.414,12 ; v1@25.27,14.496 25.27,20.27 26.1,21.1 27.2,21.1 27.375,21.275 v1(27.475,21.275) ; v1(25.27,14.496) 25.2,14.426 25.2,12.786 24.414,12 ; v1(55.05,20.925) 55.05,17.45 54.5,16.9 50.6,16.9 45.7,12 24.414,12
RESET_IN_CTRL: R73.2 U3.AD2 U7_S10.10 | length 52.2
  Top Layer w0.125: v2(21.2,24.925) 21.2,24.878 21.388,24.69 21.388,23.958 21.387,23.226 21.616,22.998 21.616,21.843 27.397,16.063 30.91,16.063 32.772,14.2 46.275,14.2 v2(46.925,14.85) ; v2(46.925,16.925) 47.106,16.925 53.381,23.2 55.66,23.2 R73.2@55.775,23.085 v2(56.225,23.085)
  Top Layer w0.15: v2(58.625,23.05) U7_S10.10@59.325,23.05
  Mid-Layer 1 w0.125: v2(21.2,24.925) 21.2,25.062 21.885,25.747 22.259,25.747 22.437,25.925 22.437,26.588 22.167,26.859 v2(22.125,26.859) ; v2(46.925,14.85) v2(46.925,16.925)
  Mid-Layer 1 w0.15: v2(56.225,23.085) 56.61,22.7 58.275,22.7 v2(58.625,23.05)
RESET_OUT_CTRL: R72.1 U3.AH2 U7_S10.2 | length 51
  Top Layer w0.125: v2(21.075,24.5) 21.075,23.185 21.366,22.894 21.366,21.74 27.293,15.813 30.806,15.813 32.669,13.95 46.7,13.95 v2(47.275,14.525) ; v2(47.075,17.375) 47.202,17.375 53.277,23.45 56.681,23.45 ; R72.1@56.7,23.085 56.7,23.432 56.681,23.45 ; U7_S10.2@57.675,23.45 56.681,23.45
  Mid-Layer 1 w0.125: v2(21.075,24.5) 20.862,24.713 20.862,25.078 21.844,26.059 v2(22.125,26.059) ; v2(47.075,17.375) 47.263,17.188 47.263,14.538 v2(47.275,14.525)
RESET_P5_BOTTOM: P11.5 SB25.2 SB26.2 | length 7.4
  Top Layer w0.15: 56,30.793 56.143,30.793 v1(56.6,31.25) 56.6,31.719 SB25.2@56.338,31.981
  Bottom Layer w0.15: v1(56.6,31.25) 57.369,30.481 P11.5@62.072,30.481
RESET_P5_TOP: P5.5 SB26.1 SB28.2 | length 8.1
  Top Layer w0.15: 55.853,30.169 56.353,30.169 ; SB28.2@56.338,28.981 56.338,30.153 56.353,30.169 ; v2(59.794,30.481) 56.869,30.481 56.557,30.169 56.353,30.169 ; v2(61.006,30.481) P5.5@62.357,30.481 P5.5@62.675,30.481
  Mid-Layer 1 w0.15: v2(59.794,30.481) v2(61.006,30.481)
RESET_TOP: P1.3 P13.6 SB27.2 SB28.1 U7_S10.16 | length 56.3
  Top Layer w0.15: SB28.1@55.662,28.981 55.4,28.719 55.4,24.67 55.595,24.475 56,24.475 U7_S10.16@57.9,24.475
  Top Layer w0.75: P13.6@33.02,3.811 P1.3@33.02,6.156 P1.3@33.02,9.086
  Bottom Layer w0.15: P13.6@33.02,3.811 34.436,2.395 46.934,2.395 49.15,4.611 49.15,13.948 50.889,15.687 55.187,15.687 57.725,18.225 57.725,23.661 56.861,24.525 v1(56.825,24.525)
SCL_EXT: R49.1 U5.12 U8_S7.7 | length 5.4
  Top Layer w0.15: U8_S7.7@98.8,33.575 98.8,33.1 v2(99.15,32.75) ; v2(100.625,32.55) 100.625,32.123 100.998,31.75 U5.12@102.585,31.75 ; R49.1@101.118,31.385 101.118,31.747
  Mid-Layer 1 w0.15: v2(99.15,32.75) 100.425,32.75 v2(100.625,32.55)
SDA_EXT: R48.1 U5.13 U8_S7.3 | length 4.5
  Top Layer w0.15: U8_S7.3@99.825,32.55 100.078,32.55 100.35,32.278 100.35,31.557 100.917,30.99 101.124,30.99 ; R48.1@101.118,30.572 101.118,30.984 101.124,30.99 ; U5.13@102.81,31.018 102.781,30.99 101.124,30.99
SHIELD_DETECT: R69.1 SB18.2 U3.AE31 | length 42.2
  Top Layer w0.125: U3.AE31@28.125,26.659 28.631,26.659 28.94,26.35 32.875,26.35 v2(33.804,25.421) ; v1(65.385,29.465) R69.1@65.385,28.55 65.862,28.55 SB18.2@66.662,27.75
  Mid-Layer 1 w0.125: v2(33.804,25.421) 37.621,25.421 41.35,29.15 v1(53.1,29.15)
  Bottom Layer w0.125: v1(53.1,29.15) 53.733,29.784 65.067,29.784 v1(65.385,29.465)
SIM_1V8: M1.19 P30.2 SB12.1 | length 20.5
  Top Layer w0.25: P30.2@107.27,11.8 112.058,11.8 112.958,12.7 115.397,12.7 116.8,14.103 v3(116.8,17.3) ; v3(117.7,18.4) 117.4,18.7 117.4,21.104 117.546,21.25 M1.19@117.975,21.25
  Top Layer w0.254: 106.24,13.945 106.762,13.422 P30.2@106.762,12.308
  Mid-Layer 1 w0.25: v3(116.8,17.3) 117.69,18.19 117.69,18.39 v3(117.7,18.4)
SIM_CLK: M1.18 P28.5 U8_S9.4 | length 49
  Top Layer w0.203: U8_S9.4@87.275,17.45 87.252,17.427 86.994,17.427 86.773,17.206 86.773,16.852 87.498,16.127 92.998,16.127 94.197,14.928 94.197,13.97 94.941,13.227 97.398,13.227 P28.5@98,12.625 ; P28.5@98,11.8 P28.5@98,12.625 ; M1.18@117.975,21.75 117.45,21.75 117,21.3 117,18.328 117.8,17.528 117.8,14.141 115.679,12.02 113.24,12.02 110.238,9.019 103.953,9.019 102.394,10.578 102.394,12.356 101.523,13.227 98.552,13.227 98,12.675 P28.5@98,12.625
SIM_IO: M1.17 P28.4 U8_S9.8 | length 47
  Top Layer w0.203: U8_S9.8@88.7,16.825 92.764,16.825 94.525,15.064 94.525,14.175 v2(94.775,13.925) 95.145,13.555 97.738,13.555 97.844,13.448 98.156,13.448 98.262,13.555 101.659,13.555 102.722,12.492 102.722,10.714 104.089,9.347 110.102,9.347 113.104,12.348 115.543,12.348 117.3,14.106 117.3,17.5 116.672,18.128 116.672,21.672 117.25,22.25 M1.17@117.975,22.25
  Mid-Layer 1 w0.203: v2(94.775,13.925) 95.65,14.8 v2(96.73,14.8)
